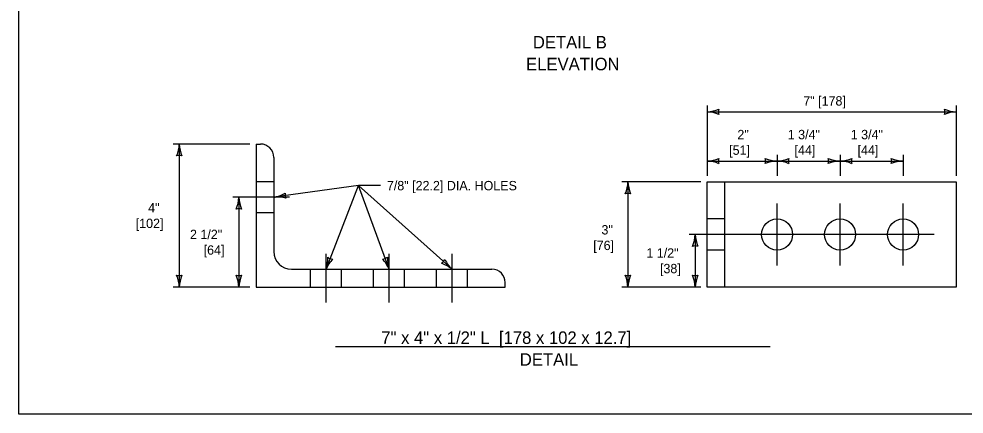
# Model space of a CAD drawing. Extents: x 49991.4 to 50021, y 49987.6 to 50011.4.
# Drawn here: x 49999.38 to 50005.46, y 49987.8 to 49990.34 of the extents above; entities that cross this region are included whole.
import ezdxf

# ---------------------------------------------------------------- set-up
doc = ezdxf.new("R2010")
doc.units = 0
for name, color, linetype in [('Level 1', 7, 'Continuous'), ('Level 2', 7, 'Continuous'), ('Level 3', 7, 'Continuous'), ('Level 4', 7, 'Continuous'), ('Level 5', 7, 'Continuous')]:
    doc.layers.add(name, color=color, linetype=linetype)

msp = doc.modelspace()

# ---------------------------------------------------------------- linework, layer by layer
at = {"layer": 'Level 1'}
for p, q in [((50000.9075, 49989.5323), (50000.9075, 49988.6143)), ((50000.9075, 49989.5323), (50000.9363, 49989.5323)), ((50001.0218, 49989.4468), (50001.0218, 49988.8429)), ((50003.8066, 49989.2893), (50005.4086, 49989.2893)), ((50003.8066, 49988.6143), (50003.8066, 49989.2893)), ((50003.9209, 49988.6143), (50003.9209, 49989.2893)), ((50005.4086, 49989.2893), (50005.4086, 49988.6143)), ((50001.1361, 49988.7286), (50002.424, 49988.7286)), ((50000.9075, 49988.6143), (50002.5095, 49988.6143)), ((50002.5095, 49988.6143), (50002.5095, 49988.6431)), ((50005.4086, 49988.6143), (50003.8066, 49988.6143))]:
    msp.add_line(p, q, dxfattribs=at)
msp.add_lwpolyline([(49999.3835, 49998.9992), (50016.7501, 49998.9992), (50016.7501, 49987.7988), (49999.3835, 49987.7988)], close=True, dxfattribs=at)
for centre in [(50004.2566, 49988.9518), (50004.6616, 49988.9518), (50005.0666, 49988.9518)]:
    msp.add_circle(centre, 0.0999, dxfattribs=at)
for centre, radius, start, end in [((50000.9363, 49989.4468), 0.0855, 0, 90), ((50001.1361, 49988.8429), 0.1143, 180, 270), ((50002.424, 49988.6431), 0.0855, 0, 90)]:
    msp.add_arc(centre, radius, start, end, dxfattribs=at)
at = {"layer": 'Level 2'}
msp.add_line((50001.4194, 49988.2334), (50004.212, 49988.2334), dxfattribs=at)
at = {"layer": 'Level 3'}
for p, q in [((50003.8066, 49989.7794), (50003.8066, 49989.3293)), ((50005.4086, 49989.7794), (50005.4086, 49989.3293)), ((50003.8066, 49989.7394), (50005.4086, 49989.7394)), ((50000.8675, 49989.5323), (50000.3743, 49989.5323)), ((50000.4143, 49989.5323), (50000.4143, 49988.6143)), ((50004.2566, 49989.4633), (50004.2566, 49989.3293)), ((50004.6616, 49989.4633), (50004.6616, 49989.3293)), ((50005.0666, 49989.4633), (50005.0666, 49989.3293)), ((50003.8066, 49989.4233), (50004.2566, 49989.4233)), ((50004.2566, 49989.4233), (50004.6616, 49989.4233)), ((50004.6616, 49989.4233), (50005.0666, 49989.4233)), ((50001.5652, 49989.2655), (50001.0218, 49989.1903)), ((50001.3575, 49988.7286), (50001.5652, 49989.2655)), ((50001.7087, 49989.2655), (50001.5652, 49989.2655)), ((50001.7625, 49988.7286), (50001.5652, 49989.2655)), ((50001.5652, 49989.2655), (50002.1675, 49988.7286)), ((50003.7666, 49989.2893), (50003.258, 49989.2893)), ((50003.298, 49989.2893), (50003.298, 49988.6143)), ((50000.7975, 49989.1903), (50000.7975, 49988.6143)), ((50003.7306, 49988.9518), (50003.7306, 49988.6143)), ((50000.8675, 49988.6143), (50000.3743, 49988.6143)), ((50003.7666, 49988.6143), (50003.258, 49988.6143))]:
    msp.add_line(p, q, dxfattribs=at)
for centre, radius, start, end in [((50003.7951, 49989.9721), 0.233, 272.82731, 292.07716), ((50003.9348, 49989.7394), 0.0548, 162.13882, 197.86118), ((50005.4178, 49989.9616), 0.2223, 247.45601, 267.63952), ((50005.2804, 49989.7394), 0.0548, 342.13882, 17.86118), ((50003.7974, 49989.5173), 0.2223, 67.45601, 87.63952), ((50005.4201, 49989.5067), 0.233, 92.82731, 112.07716), ((50000.1922, 49989.5414), 0.2223, 337.45601, 357.63952), ((50000.647, 49989.5438), 0.233, 182.82731, 202.07716), ((50000.4143, 49989.4041), 0.0548, 72.13882, 107.86118), ((50003.7951, 49989.656), 0.233, 272.82731, 292.07716), ((50003.9348, 49989.4233), 0.0548, 162.13882, 197.86118), ((50004.2658, 49989.6454), 0.2223, 247.45601, 267.63952), ((50004.1284, 49989.4233), 0.0548, 342.13882, 17.86118), ((50004.2451, 49989.656), 0.233, 272.82731, 292.07716), ((50004.3848, 49989.4233), 0.0548, 162.13882, 197.86118), ((50004.6708, 49989.6454), 0.2223, 247.45601, 267.63952), ((50004.5334, 49989.4233), 0.0548, 342.13882, 17.86118), ((50004.6501, 49989.656), 0.233, 272.82731, 292.07716), ((50004.7898, 49989.4233), 0.0548, 162.13882, 197.86118), ((50005.0758, 49989.6454), 0.2223, 247.45601, 267.63952), ((50004.9384, 49989.4233), 0.0548, 342.13882, 17.86118), ((50003.7974, 49989.2011), 0.2223, 67.45601, 87.63952), ((50004.2681, 49989.1906), 0.233, 92.82731, 112.07716), ((50004.2474, 49989.2011), 0.2223, 67.45601, 87.63952), ((50004.6731, 49989.1906), 0.233, 92.82731, 112.07716), ((50004.6524, 49989.2011), 0.2223, 67.45601, 87.63952), ((50005.0781, 49989.1906), 0.233, 92.82731, 112.07716), ((50003.0759, 49989.2984), 0.2223, 337.45601, 357.63952), ((50003.5307, 49989.3008), 0.233, 182.82731, 202.07716), ((50000.9785, 49989.4192), 0.233, 280.70747, 299.95732), ((50001.1488, 49989.2078), 0.0548, 170.01898, 205.74134), ((50003.298, 49989.1611), 0.0548, 72.13882, 107.86118), ((50000.5754, 49989.1994), 0.2223, 337.45601, 357.63952), ((50001.0302, 49989.2018), 0.233, 182.82731, 202.07716), ((50001.0432, 49988.969), 0.2223, 75.33617, 95.51968), ((50000.7975, 49989.0621), 0.0548, 72.13882, 107.86118), ((50003.5085, 49988.9609), 0.2223, 337.45601, 357.63952), ((50003.9633, 49988.9633), 0.233, 182.82731, 202.07716), ((50003.7306, 49988.8236), 0.0548, 72.13882, 107.86118), ((50001.1363, 49988.8018), 0.233, 341.68045, 0.9303), ((50001.5614, 49988.6399), 0.2223, 136.30915, 156.49266), ((50001.4037, 49988.8481), 0.0548, 230.99196, 266.71432), ((50001.7183, 49988.8489), 0.0548, 272.31774, 308.0401), ((50001.548, 49988.6375), 0.233, 23.00623, 42.25608), ((50001.9741, 49988.7966), 0.2223, 177.63493, 197.81844), ((50002.0718, 49988.8139), 0.0548, 300.42497, 336.14733), ((50002.3221, 49988.8883), 0.2223, 205.74216, 225.92567), ((50002.0212, 49988.5472), 0.233, 51.11346, 70.36331), ((50000.4143, 49988.7425), 0.0548, 252.13882, 287.86118), ((50000.1816, 49988.6028), 0.233, 2.82731, 22.07716), ((50000.6364, 49988.6051), 0.2223, 157.45601, 177.63952), ((50000.7975, 49988.7425), 0.0548, 252.13882, 287.86118), ((50000.5648, 49988.6028), 0.233, 2.82731, 22.07716), ((50001.0196, 49988.6051), 0.2223, 157.45601, 177.63952), ((50003.298, 49988.7425), 0.0548, 252.13882, 287.86118), ((50003.0653, 49988.6028), 0.233, 2.82731, 22.07716), ((50003.5202, 49988.6051), 0.2223, 157.45601, 177.63952), ((50003.7306, 49988.7425), 0.0548, 252.13882, 287.86118), ((50003.4979, 49988.6028), 0.233, 2.82731, 22.07716), ((50003.9527, 49988.6051), 0.2223, 157.45601, 177.63952)]:
    msp.add_arc(centre, radius, start, end, dxfattribs=at)
at = {"layer": 'Level 4'}
for p, q in [((50001.0218, 49989.2902), (50000.9075, 49989.2902)), ((50001.0218, 49989.0904), (50000.9075, 49989.0904)), ((50003.9209, 49989.0517), (50003.8066, 49989.0517)), ((50003.9209, 49988.8519), (50003.8066, 49988.8519)), ((50001.2576, 49988.6143), (50001.2576, 49988.7286)), ((50001.4574, 49988.6143), (50001.4574, 49988.7286)), ((50001.6626, 49988.6143), (50001.6626, 49988.7286)), ((50001.8624, 49988.6143), (50001.8624, 49988.7286)), ((50002.0676, 49988.6143), (50002.0676, 49988.7286)), ((50002.2674, 49988.6143), (50002.2674, 49988.7286))]:
    msp.add_line(p, q, dxfattribs=at)
at = {"layer": 'Level 5'}
for p, q in [((50001.1218, 49989.1903), (50000.7575, 49989.1903)), ((50004.2566, 49988.7519), (50004.2566, 49989.1517)), ((50004.6616, 49988.7519), (50004.6616, 49989.1517)), ((50005.0666, 49988.7519), (50005.0666, 49989.1517)), ((50005.2665, 49988.9518), (50003.6906, 49988.9518)), ((50001.3575, 49988.5143), (50001.3575, 49988.8286)), ((50001.7625, 49988.5143), (50001.7625, 49988.8286)), ((50002.1675, 49988.5143), (50002.1675, 49988.8286))]:
    msp.add_line(p, q, dxfattribs=at)

# ---------------------------------------------------------------- texts
at = {"layer": 'Level 2'}
for s, height, p in [('DETAIL B', 0.08, (50002.6869, 49990.1461)), ('ELEVATION', 0.08, (50002.6435, 49990.0061)), ('7" [178]', 0.06, (50004.4251, 49989.7794)), ('2"', 0.06, (50004.0017, 49989.5633)), ('1 3/4"', 0.06, (50004.3251, 49989.5633)), ('1 3/4"', 0.06, (50004.7301, 49989.5633)), ('[51]', 0.06, (50003.9487, 49989.4633)), ('[44]', 0.06, (50004.3689, 49989.4633)), ('[44]', 0.06, (50004.7739, 49989.4633)), ('7/8" [22.2] DIA. HOLES', 0.06, (50001.7487, 49989.2355)), ('4"', 0.06, (50000.2142, 49989.0932)), ('[102]', 0.06, (50000.1343, 49988.9932)), ('2 1/2"', 0.06, (50000.4833, 49988.9223)), ('3"', 0.06, (50003.1279, 49988.9518)), ('[76]', 0.06, (50003.075, 49988.8518)), ('[64]', 0.06, (50000.5709, 49988.8223)), ('1 1/2"', 0.06, (50003.4165, 49988.803)), ('[38]', 0.06, (50003.504, 49988.703)), ('7" x 4" x 1/2" L  [178 x 102 x 12.7]', 0.08, (50001.7128, 49988.2494)), ('DETAIL', 0.08, (50002.603, 49988.1094))]:
    msp.add_text(s, height=height, dxfattribs=at).set_placement(p)

doc.saveas('drawing.dxf')
